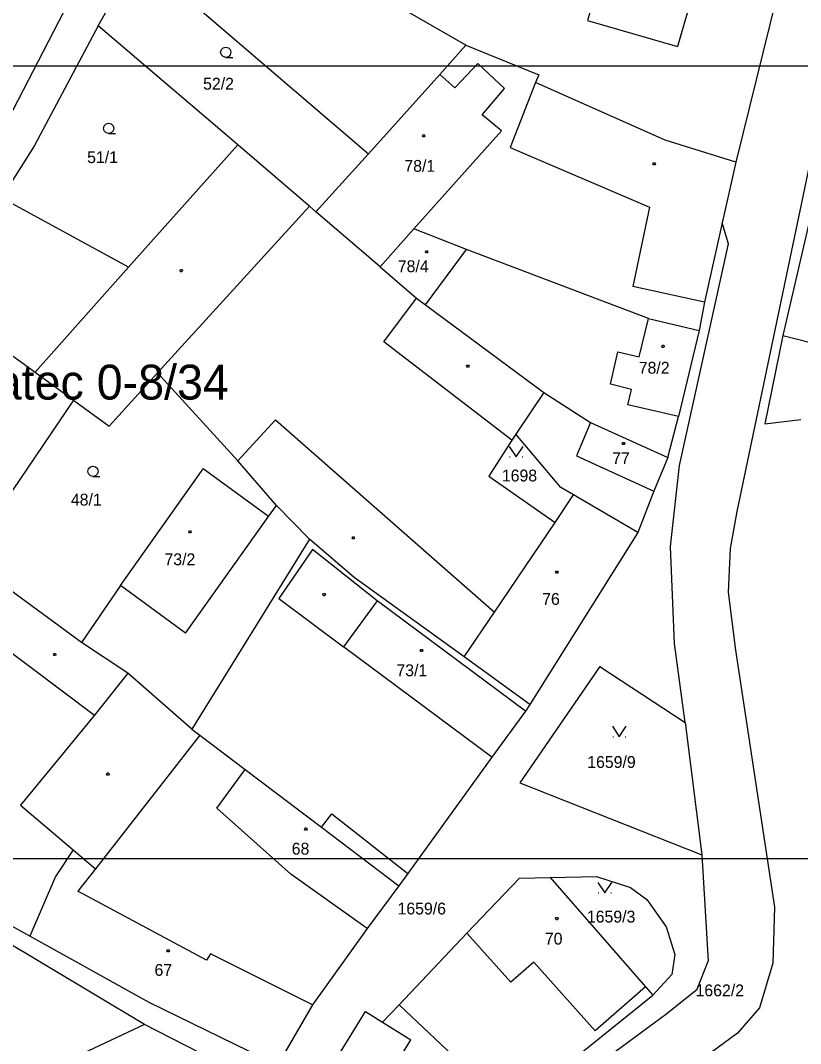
# Model space of a CAD drawing. Extents: x -802857 to -799647, y -1020285 to -1015884.
# Drawn here: x -801601.9 to -801490, y -1017640.2 to -1017493.5 of the extents above; entities that cross this region are included whole.
import ezdxf

# ---------------------------------------------------------------- set-up
doc = ezdxf.new("R2010")
doc.units = 0
for name, color, linetype in [('Default', 7, 'Continuous'), ('KLADY_ZMVM', 7, 'Continuous'), ('KN_HRANICE', 7, 'Continuous'), ('KN_KULTURY', 7, 'Continuous'), ('KN_PARCELY', 7, 'Continuous'), ('KN_SLUCKY', 7, 'Continuous'), ('LEGENDA', 7, 'Continuous')]:
    doc.layers.add(name, color=color, linetype=linetype)

# ---------------------------------------------------------------- blocks, each defined once
blk = doc.blocks.new('304')
at = {"layer": 'Default'}
blk.add_lwpolyline([(0, 0), (-0.38, 0.1), (-0.65, 0.37), (-0.75, 0.74), (-0.65, 1.11), (-0.38, 1.38), (-0.01, 1.48), (0.36, 1.38), (0.63, 1.11), (0.73, 0.73), (0.63, 0.35), (0.36, 0.08), (-0.02, -0.02), (0.98, -0.02)], dxfattribs=at)
blk = doc.blocks.new('314')
at = {"layer": 'Default'}
for p, q in [((-0.95, 0), (-0.85, 0)), ((0.85, 0), (0.95, 0))]:
    blk.add_line(p, q, dxfattribs=at)
blk.add_lwpolyline([(-1, 1.5), (0, 0), (1, 1.5)], dxfattribs=at)
blk = doc.blocks.new('NAHRADNI_SYMBOL')
at = {"layer": 'Default'}
blk.add_lwpolyline([(0.09, 0.15), (0.18, 0), (0.09, -0.15), (-0.09, -0.15), (-0.18, 0), (-0.09, 0.15), (0.09, 0.15)], dxfattribs=at)
blk = doc.blocks.new('402')
at = {"layer": 'Default'}
blk.add_lwpolyline([(0.09, 0.15), (0.18, 0), (0.09, -0.15), (-0.09, -0.15), (-0.18, 0), (-0.09, 0.15), (0.09, 0.15)], dxfattribs=at)

msp = doc.modelspace()

# ---------------------------------------------------------------- linework, layer by layer
at = {"layer": 'KLADY_ZMVM'}
msp.add_lwpolyline([(-801875, -1017500), (-801250, -1017500), (-801043.11, -1017500)], dxfattribs=at)
at = {"layer": 'KN_HRANICE'}
for p, q in [((-801590.76, -1017494.27), (-801585.19, -1017484.18)), ((-801585.19, -1017484.18), (-801552, -1017512.59)), ((-801518.48, -1017486.31), (-801520.55, -1017493.48)), ((-801538.03, -1017497.01), (-801552.91, -1017488.45)), ((-801493.16, -1017489.06), (-801499.29, -1017513.8)), ((-801505.75, -1017490.62), (-801507.63, -1017497.2)), ((-801603.69, -1017507.7), (-801595.69, -1017492.25)), ((-801520.55, -1017493.48), (-801507.63, -1017497.2)), ((-801590.76, -1017494.27), (-801599.92, -1017511.43)), ((-801570.74, -1017511.34), (-801590.76, -1017494.27)), ((-801538.03, -1017497.01), (-801541.73, -1017501.25)), ((-801538.03, -1017497.01), (-801527.53, -1017501.29)), ((-801485.05, -1017496.6), (-801499.12, -1017563.93)), ((-801541.73, -1017501.25), (-801552, -1017512.59)), ((-801527.53, -1017501.29), (-801528.03, -1017502.37)), ((-801509.4, -1017510.64), (-801528.03, -1017502.37)), ((-801499.29, -1017513.8), (-801509.4, -1017510.64)), ((-801599.92, -1017511.43), (-801604.62, -1017518.91)), ((-801586.4, -1017528.88), (-801570.74, -1017511.34)), ((-801560.61, -1017519.98), (-801570.74, -1017511.34)), ((-801559.52, -1017520.91), (-801552, -1017512.59)), ((-801499.29, -1017513.8), (-801501.23, -1017522.53)), ((-801586.4, -1017528.88), (-801604.62, -1017518.91)), ((-801560.46, -1017520.1), (-801560.61, -1017519.98)), ((-801559.52, -1017520.91), (-801560.46, -1017520.1)), ((-801550.32, -1017528.8), (-801559.52, -1017520.91)), ((-801501.23, -1017522.53), (-801503.76, -1017533.9)), ((-801500.33, -1017525.52), (-801501.23, -1017522.53)), ((-801488.6, -1017521.78), (-801492.54, -1017538.69)), ((-801545.46, -1017523.36), (-801550.32, -1017528.8)), ((-801537.9, -1017526.32), (-801545.46, -1017523.36)), ((-801507.37, -1017557.32), (-801500.33, -1017525.52)), ((-801543.79, -1017534.25), (-801537.9, -1017526.32)), ((-801511.78, -1017536.22), (-801537.9, -1017526.32)), ((-801599.81, -1017543.92), (-801586.4, -1017528.88)), ((-801550.32, -1017528.8), (-801545.07, -1017533.3)), ((-801612.51, -1017534.74), (-801599.81, -1017543.92)), ((-801545.07, -1017533.3), (-801543.79, -1017534.25)), ((-801543.79, -1017534.25), (-801526.81, -1017546.86)), ((-801503.76, -1017533.9), (-801504.53, -1017537.97)), ((-801511.78, -1017536.22), (-801504.53, -1017537.97)), ((-801504.53, -1017537.97), (-801507.52, -1017550.31)), ((-801492.54, -1017538.69), (-801495.13, -1017551.32)), ((-801492.54, -1017538.69), (-801482.76, -1017541.15)), ((-801599.81, -1017543.92), (-801594.29, -1017547.96)), ((-801589.21, -1017551.68), (-801582.27, -1017544.05)), ((-801570.72, -1017556.63), (-801582.27, -1017544.05)), ((-801594.29, -1017547.96), (-801609.85, -1017570.88)), ((-801594.29, -1017547.96), (-801589.21, -1017551.68)), ((-801526.81, -1017546.86), (-801530.84, -1017552.81)), ((-801526.81, -1017546.86), (-801520.11, -1017551.13)), ((-801509.03, -1017556.19), (-801507.52, -1017550.31)), ((-801495.13, -1017551.32), (-801489.95, -1017550.72)), ((-801520.11, -1017551.13), (-801509.03, -1017556.19)), ((-801531.4, -1017553.68), (-801534.73, -1017558.85)), ((-801530.84, -1017552.81), (-801531.4, -1017553.68)), ((-801524.36, -1017560.49), (-801530.84, -1017552.81)), ((-801565.19, -1017563.07), (-801570.72, -1017556.63)), ((-801509.03, -1017556.19), (-801511.04, -1017561)), ((-801587.58, -1017574.55), (-801575.7, -1017557.81)), ((-801566.34, -1017564.62), (-801575.7, -1017557.81)), ((-801508.64, -1017568.95), (-801507.37, -1017557.32)), ((-801534.73, -1017558.85), (-801525.21, -1017565.48)), ((-801522.55, -1017561.54), (-801524.36, -1017560.49)), ((-801511.04, -1017561), (-801513.34, -1017566.91)), ((-801525.21, -1017565.48), (-801522.55, -1017561.54)), ((-801513.34, -1017566.91), (-801522.55, -1017561.54)), ((-801566.34, -1017564.62), (-801565.19, -1017563.07)), ((-801560.45, -1017567.88), (-801565.19, -1017563.07)), ((-801499.12, -1017563.93), (-801500.06, -1017569.23)), ((-801513.34, -1017566.91), (-801528.85, -1017591.59)), ((-801560.45, -1017567.88), (-801577.33, -1017595.14)), ((-801554.01, -1017573.4), (-801560.45, -1017567.88)), ((-801508.08, -1017582.87), (-801508.64, -1017568.95)), ((-801500.06, -1017569.23), (-801500.38, -1017575.48)), ((-801538.26, -1017584.79), (-801554.01, -1017573.4)), ((-801593.16, -1017582.7), (-801603.42, -1017575.18)), ((-801587.58, -1017574.55), (-801593.16, -1017582.7)), ((-801500.38, -1017575.48), (-801499.34, -1017583.8)), ((-801606.97, -1017581.38), (-801591.28, -1017593.15)), ((-801586.53, -1017587.13), (-801593.16, -1017582.7)), ((-801506.53, -1017594.21), (-801508.08, -1017582.87)), ((-801499.34, -1017583.8), (-801493.73, -1017620.66)), ((-801528.85, -1017591.59), (-801538.26, -1017584.79)), ((-801577.33, -1017595.14), (-801586.53, -1017587.13)), ((-801518.8, -1017586.17), (-801530.24, -1017602.86)), ((-801518.8, -1017586.17), (-801506.53, -1017594.21)), ((-801528.85, -1017591.59), (-801529.45, -1017592.57)), ((-801591.28, -1017593.15), (-801601.9, -1017606.03)), ((-801529.45, -1017592.57), (-801534.26, -1017599.18)), ((-801506.53, -1017594.21), (-801504.15, -1017613.18)), ((-801577.33, -1017595.14), (-801576.17, -1017596.02)), ((-801576.17, -1017596.02), (-801569.65, -1017600.94)), ((-801534.26, -1017599.18), (-801546.35, -1017615.83)), ((-801573.76, -1017606.48), (-801569.65, -1017600.94)), ((-801569.65, -1017600.94), (-801558.71, -1017609.22)), ((-801530.24, -1017602.86), (-801504.15, -1017613.18)), ((-801601.9, -1017606.03), (-801594.36, -1017612.44)), ((-801563.14, -1017615.95), (-801573.76, -1017606.48)), ((-801594.36, -1017612.44), (-801596.9, -1017616.29)), ((-801504.15, -1017613.18), (-801503.26, -1017628.41)), ((-801584.1, -1017637.52), (-801621.52, -1017615.14)), ((-801600.56, -1017624.82), (-801620.3, -1017614.03)), ((-801596.9, -1017616.29), (-801600.56, -1017624.82)), ((-801552.18, -1017623.73), (-801563.14, -1017615.95)), ((-801546.35, -1017615.83), (-801547.64, -1017617.6)), ((-801537.86, -1017624.4), (-801530.31, -1017616.54)), ((-801530.31, -1017616.54), (-801525.93, -1017616.44)), ((-801525.93, -1017616.44), (-801519.25, -1017616.26)), ((-801525.93, -1017616.44), (-801512.24, -1017632.12)), ((-801519.25, -1017616.26), (-801514.39, -1017617.87)), ((-801547.64, -1017617.6), (-801552.18, -1017623.73)), ((-801514.39, -1017617.87), (-801512.04, -1017619.58)), ((-801512.04, -1017619.58), (-801509.28, -1017623.48)), ((-801493.73, -1017620.66), (-801493.97, -1017628.73)), ((-801552.18, -1017623.73), (-801560.01, -1017634.67)), ((-801509.28, -1017623.48), (-801508.02, -1017627.49)), ((-801583.43, -1017634.37), (-801600.56, -1017624.82)), ((-801537.86, -1017624.4), (-801547.58, -1017634.67)), ((-801508.02, -1017627.49), (-801508.47, -1017630.35)), ((-801504.84, -1017632.45), (-801503.26, -1017628.41)), ((-801493.97, -1017628.73), (-801495.87, -1017635.14)), ((-801508.47, -1017630.35), (-801511.2, -1017633.31)), ((-801512.24, -1017632.12), (-801511.2, -1017633.31)), ((-801509.19, -1017635.93), (-801504.84, -1017632.45)), ((-801565.01, -1017643.36), (-801583.43, -1017634.37)), ((-801531.59, -1017649.73), (-801511.2, -1017633.31)), ((-801560.01, -1017634.67), (-801565.01, -1017643.36)), ((-801560.79, -1017649.3), (-801552.43, -1017635.64)), ((-801552.43, -1017635.64), (-801549.96, -1017637.17)), ((-801547.58, -1017634.67), (-801549.96, -1017637.17)), ((-801547.58, -1017634.67), (-801531.59, -1017649.73)), ((-801517.33, -1017641.94), (-801509.19, -1017635.93)), ((-801495.87, -1017635.14), (-801499.03, -1017638.78)), ((-801584.1, -1017637.52), (-801594.58, -1017642.43)), ((-801569.55, -1017644.94), (-801584.1, -1017637.52)), ((-801499.03, -1017638.78), (-801510.49, -1017647.16))]:
    msp.add_line(p, q, dxfattribs=at)
msp.add_lwpolyline([(-801558.71, -1017609.22), (-801557.22, -1017607.3), (-801546.35, -1017615.83)], dxfattribs=at)
at = {"layer": 'KN_SLUCKY'}
for p, q in [((-801536.3, -1017499.67), (-801539.59, -1017503.13)), ((-801532.44, -1017503.25), (-801536.3, -1017499.67)), ((-801539.59, -1017503.13), (-801541.73, -1017501.25)), ((-801528.03, -1017502.37), (-801531.64, -1017511.71)), ((-801535.69, -1017507), (-801532.44, -1017503.25)), ((-801532.9, -1017509.3), (-801535.69, -1017507)), ((-801545.46, -1017523.36), (-801532.9, -1017509.3)), ((-801531.64, -1017511.71), (-801511.64, -1017520.27)), ((-801582.27, -1017544.05), (-801560.46, -1017520.1)), ((-801511.64, -1017520.27), (-801514.07, -1017531.66)), ((-801503.76, -1017533.9), (-801514.07, -1017531.66)), ((-801549.8, -1017539.59), (-801545.07, -1017533.3)), ((-801513.15, -1017541.75), (-801511.78, -1017536.22)), ((-801531.4, -1017553.68), (-801549.8, -1017539.59)), ((-801517.27, -1017545.66), (-801516.18, -1017541.02)), ((-801516.18, -1017541.02), (-801513.15, -1017541.75)), ((-801514.23, -1017546.41), (-801517.27, -1017545.66)), ((-801514.78, -1017548.62), (-801514.23, -1017546.41)), ((-801507.52, -1017550.31), (-801514.78, -1017548.62)), ((-801565.3, -1017550.76), (-801570.72, -1017556.63)), ((-801565.3, -1017550.76), (-801533.92, -1017578.36)), ((-801520.11, -1017551.13), (-801522.12, -1017555.94)), ((-801522.12, -1017555.94), (-801511.04, -1017561)), ((-801578.22, -1017581.36), (-801566.34, -1017564.62)), ((-801533.92, -1017578.36), (-801525.21, -1017565.48)), ((-801560.01, -1017569.37), (-801564.85, -1017576.41)), ((-801550.75, -1017576.74), (-801560.01, -1017569.37)), ((-801578.22, -1017581.36), (-801587.58, -1017574.55)), ((-801564.85, -1017576.41), (-801555.56, -1017583.35)), ((-801550.75, -1017576.74), (-801555.56, -1017583.35)), ((-801529.45, -1017592.57), (-801550.75, -1017576.74)), ((-801538.26, -1017584.79), (-801533.92, -1017578.36)), ((-801534.26, -1017599.18), (-801555.56, -1017583.35)), ((-801586.53, -1017587.13), (-801591.28, -1017593.15)), ((-801576.17, -1017596.02), (-801591.13, -1017615.17)), ((-801558.71, -1017609.22), (-801547.64, -1017617.6)), ((-801594.36, -1017612.44), (-801591.13, -1017615.17)), ((-801591.13, -1017615.17), (-801593.7, -1017618.41)), ((-801575.23, -1017628.29), (-801593.7, -1017618.41)), ((-801531.55, -1017631.46), (-801537.86, -1017624.4)), ((-801574.67, -1017627.39), (-801575.23, -1017628.29)), ((-801560.01, -1017634.67), (-801574.67, -1017627.39)), ((-801528.27, -1017628.59), (-801531.55, -1017631.46)), ((-801519.47, -1017638.44), (-801528.27, -1017628.59)), ((-801512.24, -1017632.12), (-801519.47, -1017638.44)), ((-801549.96, -1017637.17), (-801545.89, -1017639.69)), ((-801550.3, -1017646.89), (-801545.89, -1017639.69))]:
    msp.add_line(p, q, dxfattribs=at)
at = {"layer": 'LEGENDA'}
msp.add_lwpolyline([(-801703.84, -1017613.71), (-800862.84, -1017613.71), (-800862.84, -1017019.71), (-801703.84, -1017019.71)], close=True, dxfattribs=at)

# ---------------------------------------------------------------- block references
at = {"layer": 'KN_KULTURY'}
for name, p in [('304', (-801572.44, -1017498.77)), ('304', (-801589.25, -1017509.68)), ('402', (-801544.06, -1017510.03)), ('402', (-801510.98, -1017514.05)), ('NAHRADNI_SYMBOL', (-801543.64, -1017526.68)), ('402', (-801578.84, -1017529.37)), ('402', (-801509.71, -1017540.23)), ('402', (-801537.72, -1017543.08)), ('314', (-801530.79, -1017556.09)), ('402', (-801515.39, -1017554.15)), ('304', (-801591.5, -1017558.88)), ('402', (-801577.59, -1017566.83)), ('402', (-801554.15, -1017567.69)), ('402', (-801524.95, -1017572.61)), ('402', (-801558.34, -1017575.85)), ('402', (-801597, -1017584.44)), ('402', (-801544.36, -1017583.86)), ('314', (-801515.99, -1017596.23)), ('402', (-801589.39, -1017601.58)), ('402', (-801560.98, -1017609.47)), ('314', (-801518.07, -1017618.63)), ('402', (-801524.95, -1017622.33)), ('402', (-801580.71, -1017626.93))]:
    msp.add_blockref(name, p, dxfattribs=at)

# ---------------------------------------------------------------- texts
at = {"layer": 'KLADY_ZMVM'}
msp.add_text('Žatec 0-8/34', height=5, dxfattribs=at).set_placement((-801609.55, -1017547.86))
at = {"layer": 'KN_PARCELY'}
for s, p in [('52/2', (-801575.71, -1017503.4)), ('51/1', (-801592.35, -1017513.94)), ('78/1', (-801546.83, -1017515.19)), ('78/4', (-801547.77, -1017529.59)), ('78/2', (-801513.2, -1017544.15)), ('77', (-801517.01, -1017557.12)), ('1698', (-801532.84, -1017559.61)), ('48/1', (-801594.68, -1017563.07)), ('73/2', (-801581.25, -1017571.63)), ('76', (-801527.06, -1017577.32)), ('73/1', (-801547.97, -1017587.55)), ('1659/9', (-801520.59, -1017600.71)), ('68', (-801562.99, -1017613.14)), ('1659/6', (-801547.81, -1017621.73)), ('1659/3', (-801520.64, -1017622.89)), ('70', (-801526.67, -1017626.05)), ('67', (-801582.68, -1017630.54)), ('1662/2', (-801505.05, -1017633.47))]:
    msp.add_text(s, height=1.7, dxfattribs=at).set_placement(p)

doc.saveas('drawing.dxf')
